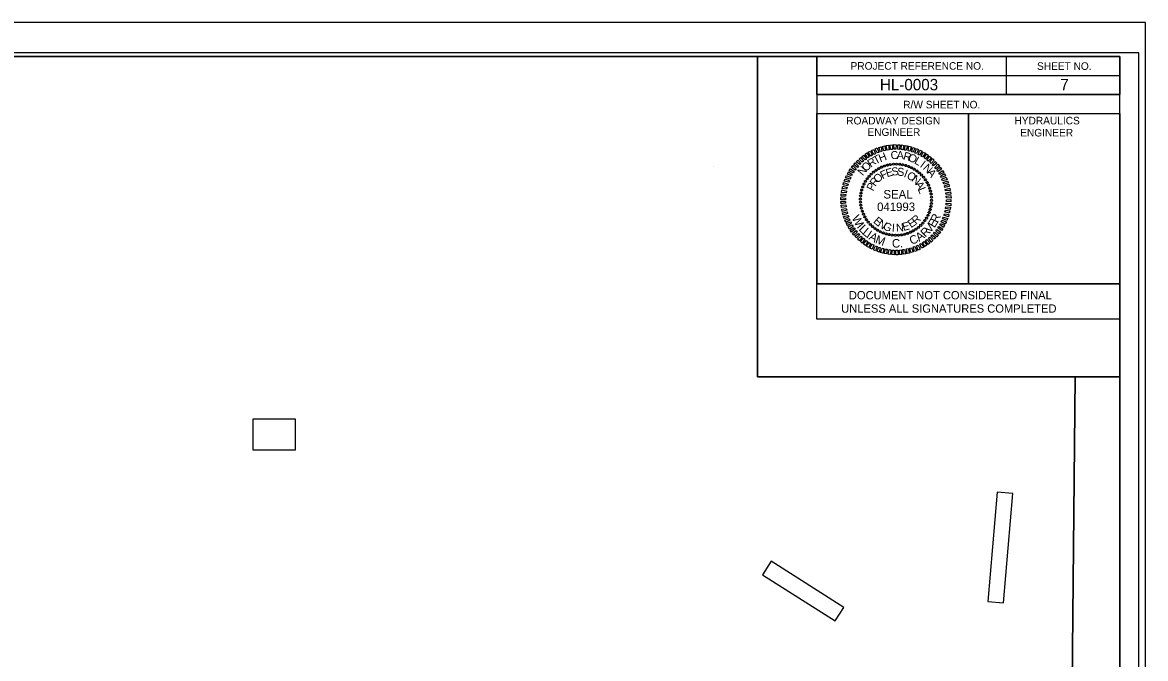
# Model space of a CAD drawing. Extents: x 928111 to 937215, y 684185 to 686530.
# Drawn here: x 932495 to 933237, y 684860 to 685280 of the extents above; entities that cross this region are included whole.
import ezdxf

# ---------------------------------------------------------------- set-up
doc = ezdxf.new("R2010")
doc.units = 0
for name, color, linetype in [('Default', 7, 'Continuous'), ('Matchline', 7, 'Continuous'), ('Prop DSN Text', 7, 'Continuous'), ('Sheet Cutting Line CELL', 7, 'Continuous'), ('Sheet Data Field CELL', 7, 'Continuous'), ('Sheet Layout Plan Border', 7, 'Continuous'), ('Sheet North Arrow Point CELL', 7, 'Continuous'), ('Sheet Plan CELL', 7, 'Continuous'), ('Sheet Plan Layout CELL', 7, 'Continuous'), ('Sheet Plot Border Outside CELL', 7, 'Continuous')]:
    doc.layers.add(name, color=color, linetype=linetype)

msp = doc.modelspace()

# ---------------------------------------------------------------- linework, layer by layer
at = {"layer": 'Default'}
for p, q in [((933060.53, 685183.66), (933060.53, 685183.66)), ((933062.36, 685184.6), (933062.36, 685184.6)), ((933064.24, 685185.35), (933064.24, 685185.35)), ((933066.2, 685185.91), (933066.2, 685185.91)), ((933068.27, 685186.29), (933068.27, 685186.29)), ((933070.28, 685186.57), (933070.28, 685186.57)), ((933072.34, 685186.62), (933072.34, 685186.62)), ((933074.41, 685186.48), (933074.41, 685186.48)), ((933076.42, 685186.15), (933076.42, 685186.15)), ((933078.39, 685185.73), (933078.39, 685185.73)), ((933080.36, 685185.07), (933080.36, 685185.07)), ((933082.24, 685184.23), (933082.24, 685184.23)), ((933052.89, 685176.91), (933052.89, 685176.91)), ((933054.16, 685178.55), (933054.16, 685178.55)), ((933055.56, 685180.01), (933055.56, 685180.01)), ((933057.11, 685181.41), (933057.11, 685181.41)), ((933058.75, 685182.59), (933058.75, 685182.59)), ((933084.06, 685183.29), (933084.06, 685183.29)), ((933085.75, 685182.12), (933085.75, 685182.12)), ((933087.39, 685180.85), (933087.39, 685180.85)), ((933088.84, 685179.45), (933088.84, 685179.45)), ((933090.25, 685177.9), (933090.25, 685177.9)), ((933091.42, 685176.26), (933091.42, 685176.26)), ((933049.28, 685169.55), (933049.28, 685169.55)), ((933049.94, 685171.52), (933049.94, 685171.52)), ((933050.78, 685173.4), (933050.78, 685173.4)), ((933051.72, 685175.23), (933051.72, 685175.23)), ((933092.5, 685174.48), (933092.5, 685174.48)), ((933093.44, 685172.65), (933093.44, 685172.65)), ((933094.19, 685170.77), (933094.19, 685170.77)), ((933048.39, 685163.51), (933048.39, 685163.51)), ((933048.44, 685161.45), (933048.44, 685161.45)), ((933048.53, 685165.57), (933048.53, 685165.57)), ((933048.86, 685167.59), (933048.86, 685167.59)), ((933071.92, 685163.09), (933071.92, 685163.09)), ((933094.75, 685168.8), (933094.75, 685168.8)), ((933095.13, 685166.74), (933095.13, 685166.74)), ((933095.41, 685164.73), (933095.41, 685164.73)), ((933095.45, 685162.66), (933095.45, 685162.66)), ((933048.72, 685159.43), (933048.72, 685159.43)), ((933049.09, 685157.37), (933049.09, 685157.37)), ((933049.66, 685155.4), (933049.66, 685155.4)), ((933093.91, 685154.65), (933093.91, 685154.65)), ((933094.56, 685156.62), (933094.56, 685156.62)), ((933094.99, 685158.59), (933094.99, 685158.59)), ((933095.31, 685160.6), (933095.31, 685160.6)), ((933050.41, 685153.52), (933050.41, 685153.52)), ((933051.34, 685151.7), (933051.34, 685151.7)), ((933052.42, 685149.91), (933052.42, 685149.91)), ((933053.59, 685148.27), (933053.59, 685148.27)), ((933055, 685146.73), (933055, 685146.73)), ((933089.69, 685147.62), (933089.69, 685147.62)), ((933090.95, 685149.26), (933090.95, 685149.26)), ((933092.13, 685150.95), (933092.13, 685150.95)), ((933093.06, 685152.77), (933093.06, 685152.77)), ((933056.45, 685145.32), (933056.45, 685145.32)), ((933058.09, 685144.05), (933058.09, 685144.05)), ((933059.78, 685142.88), (933059.78, 685142.88)), ((933061.61, 685141.95), (933061.61, 685141.95)), ((933063.49, 685141.1), (933063.49, 685141.1)), ((933065.45, 685140.45), (933065.45, 685140.45)), ((933067.42, 685140.02), (933067.42, 685140.02)), ((933069.44, 685139.7), (933069.44, 685139.7)), ((933071.5, 685139.55), (933071.5, 685139.55)), ((933073.56, 685139.6), (933073.56, 685139.6)), ((933075.58, 685139.88), (933075.58, 685139.88)), ((933077.64, 685140.26), (933077.64, 685140.26)), ((933079.61, 685140.82), (933079.61, 685140.82)), ((933081.49, 685141.57), (933081.49, 685141.57)), ((933083.31, 685142.51), (933083.31, 685142.51)), ((933085.09, 685143.59), (933085.09, 685143.59)), ((933086.74, 685144.76), (933086.74, 685144.76)), ((933088.28, 685146.16), (933088.28, 685146.16))]:
    msp.add_line(p, q, dxfattribs=at)
for points in [[(933063.95, 685195.38), (933062.97, 685198.34), (933064.56, 685198.66), (933064.94, 685195.62)], [(933066.2, 685195.9), (933065.45, 685198.9), (933067, 685199.04), (933067.33, 685196.04)], [(933068.45, 685196.18), (933067.94, 685199.18), (933069.53, 685199.37), (933069.58, 685196.32)], [(933070.8, 685196.41), (933070.56, 685199.46), (933072.11, 685199.41), (933071.92, 685196.37)], [(933073.05, 685196.37), (933073.05, 685199.41), (933074.59, 685199.37), (933074.17, 685196.32)], [(933075.39, 685196.23), (933075.58, 685199.27), (933077.13, 685198.99), (933076.52, 685196.04)], [(933077.64, 685195.85), (933078.06, 685198.85), (933079.61, 685198.62), (933078.77, 685195.71)], [(933051.49, 685189.34), (933049.47, 685191.59), (933050.74, 685192.57), (933052.38, 685189.95)], [(933053.27, 685190.74), (933051.53, 685193.13), (933052.75, 685194.02), (933054.3, 685191.3)], [(933055.33, 685191.91), (933053.59, 685194.45), (933055.05, 685195.2), (933056.22, 685192.48)], [(933057.34, 685193.04), (933055.84, 685195.66), (933057.3, 685196.32), (933058.38, 685193.46)], [(933059.41, 685194.02), (933058.19, 685196.74), (933059.59, 685197.3), (933060.58, 685194.3)], [(933061.7, 685194.77), (933060.63, 685197.59), (933062.08, 685198.01), (933062.69, 685195.1)], [(933080.03, 685195.34), (933080.5, 685198.38), (933082.09, 685198.01), (933081.02, 685195.1)], [(933082.28, 685194.73), (933082.99, 685197.63), (933084.44, 685197.16), (933083.27, 685194.4)], [(933084.39, 685193.88), (933085.47, 685196.84), (933086.78, 685196.27), (933085.47, 685193.55)], [(933086.5, 685192.99), (933087.67, 685195.76), (933089.13, 685195.1), (933087.53, 685192.48)], [(933088.66, 685191.91), (933089.92, 685194.59), (933091.33, 685193.79), (933089.55, 685191.35)], [(933090.49, 685190.65), (933092.13, 685193.37), (933093.34, 685192.38), (933091.52, 685190.09)], [(933092.41, 685189.24), (933094.14, 685191.82), (933095.36, 685190.79), (933093.3, 685188.59)], [(933045.02, 685182.68), (933042.49, 685184.27), (933043.38, 685185.63), (933045.63, 685183.57)], [(933046.42, 685184.46), (933043.99, 685186.29), (933045.02, 685187.51), (933047.08, 685185.3)], [(933048.06, 685186.24), (933045.67, 685188.16), (933046.84, 685189.24), (933048.81, 685186.99)], [(933049.61, 685187.88), (933047.55, 685189.95), (933048.67, 685191.07), (933050.5, 685188.54)], [(933094.19, 685187.79), (933096.11, 685190.23), (933097.24, 685189.1), (933095.08, 685187.09)], [(933095.88, 685186.15), (933097.89, 685188.35), (933099.02, 685187.23), (933096.58, 685185.4)], [(933097.52, 685184.46), (933099.67, 685186.57), (933100.66, 685185.3), (933098.17, 685183.52)], [(933098.92, 685182.63), (933101.22, 685184.6), (933102.11, 685183.24), (933099.49, 685181.74)], [(933040.61, 685174.57), (933037.7, 685175.41), (933038.31, 685176.87), (933041.13, 685175.55)], [(933041.55, 685176.63), (933038.64, 685177.71), (933039.34, 685179.16), (933042.02, 685177.66)], [(933042.49, 685178.79), (933039.81, 685179.96), (933040.52, 685181.41), (933043.05, 685179.68)], [(933043.61, 685180.8), (933040.99, 685182.21), (933041.92, 685183.52), (933044.36, 685181.65)], [(933100.14, 685180.71), (933102.63, 685182.49), (933103.52, 685181.09), (933100.8, 685179.77)], [(933101.36, 685178.65), (933103.99, 685180.29), (933104.59, 685178.84), (933101.92, 685177.76)], [(933102.3, 685176.63), (933105.06, 685178.04), (933105.67, 685176.54), (933102.77, 685175.6)], [(933038.92, 685167.68), (933035.92, 685167.96), (933036.11, 685169.55), (933039.16, 685168.8)], [(933039.3, 685170.07), (933036.39, 685170.45), (933036.72, 685172.04), (933039.67, 685171.05)], [(933039.91, 685172.32), (933037, 685172.93), (933037.33, 685174.48), (933040.28, 685173.3)], [(933103.14, 685174.43), (933106, 685175.65), (933106.52, 685174.2), (933103.61, 685173.45)], [(933103.89, 685172.18), (933106.89, 685173.26), (933107.17, 685171.71), (933104.22, 685171.2)], [(933104.45, 685169.93), (933107.41, 685170.82), (933107.69, 685169.23), (933104.74, 685168.95)], [(933038.69, 685160.74), (933035.64, 685160.37), (933035.55, 685161.96), (933038.59, 685161.87)], [(933038.64, 685163.09), (933035.59, 685162.95), (933035.59, 685164.54), (933038.64, 685164.21)], [(933038.69, 685165.43), (933035.64, 685165.52), (933035.74, 685167.07), (933038.78, 685166.55)], [(933104.88, 685167.68), (933107.92, 685168.34), (933108.06, 685166.74), (933105.06, 685166.55)], [(933105.16, 685165.43), (933108.2, 685165.8), (933108.3, 685164.21), (933105.25, 685164.3)], [(933105.2, 685163.09), (933108.25, 685163.23), (933108.25, 685161.63), (933105.2, 685161.96)], [(933038.97, 685158.49), (933035.92, 685157.84), (933035.78, 685159.43), (933038.78, 685159.62)], [(933039.39, 685156.24), (933036.44, 685155.35), (933036.16, 685156.95), (933039.11, 685157.23)], [(933039.95, 685153.99), (933036.95, 685152.91), (933036.67, 685154.46), (933039.63, 685154.98)], [(933104.55, 685156.1), (933107.45, 685155.73), (933107.13, 685154.13), (933104.17, 685155.12)], [(933104.92, 685158.49), (933107.92, 685158.21), (933107.74, 685156.62), (933104.69, 685157.37)], [(933105.16, 685160.74), (933108.2, 685160.65), (933108.11, 685159.1), (933105.06, 685159.62)], [(933040.7, 685151.74), (933037.84, 685150.52), (933037.33, 685151.98), (933040.24, 685152.73)], [(933041.55, 685149.54), (933038.78, 685148.13), (933038.17, 685149.63), (933041.08, 685150.57)], [(933042.49, 685147.52), (933039.86, 685145.88), (933039.25, 685147.34), (933041.92, 685148.41)], [(933101.36, 685147.38), (933104.03, 685146.21), (933103.33, 685144.76), (933100.8, 685146.49)], [(933102.3, 685149.54), (933105.2, 685148.46), (933104.5, 685147.01), (933101.83, 685148.51)], [(933103.24, 685151.6), (933106.14, 685150.76), (933105.53, 685149.3), (933102.72, 685150.62)], [(933103.94, 685153.85), (933106.84, 685153.24), (933106.52, 685151.7), (933103.56, 685152.87)], [(933043.7, 685145.46), (933041.22, 685143.68), (933040.33, 685145.09), (933043.05, 685146.4)], [(933044.92, 685143.54), (933042.63, 685141.57), (933041.74, 685142.93), (933044.36, 685144.43)], [(933046.33, 685141.71), (933044.17, 685139.6), (933043.19, 685140.87), (933045.67, 685142.65)], [(933047.97, 685140.02), (933045.95, 685137.82), (933044.83, 685138.95), (933047.27, 685140.77)], [(933095.78, 685139.93), (933098.17, 685138.01), (933097, 685136.93), (933095.03, 685139.18)], [(933097.42, 685141.71), (933099.86, 685139.88), (933098.83, 685138.66), (933096.77, 685140.87)], [(933098.83, 685143.49), (933101.36, 685141.9), (933100.47, 685140.54), (933098.22, 685142.6)], [(933100.24, 685145.37), (933102.86, 685143.96), (933101.92, 685142.65), (933099.49, 685144.52)], [(933049.66, 685138.38), (933047.74, 685135.95), (933046.61, 685137.07), (933048.77, 685139.09)], [(933051.44, 685136.93), (933049.7, 685134.35), (933048.49, 685135.38), (933050.55, 685137.59)], [(933053.36, 685135.52), (933051.72, 685132.8), (933050.5, 685133.79), (933052.33, 685136.09)], [(933055.19, 685134.26), (933053.92, 685131.59), (933052.52, 685132.38), (933054.3, 685134.82)], [(933057.34, 685133.18), (933056.17, 685130.41), (933054.72, 685131.07), (933056.31, 685133.7)], [(933059.45, 685132.29), (933058.38, 685129.34), (933057.06, 685129.9), (933058.38, 685132.62)], [(933061.56, 685131.45), (933060.86, 685128.54), (933059.41, 685129.01), (933060.58, 685131.77)], [(933084.44, 685132.15), (933085.66, 685129.43), (933084.25, 685128.87), (933083.27, 685131.87)], [(933086.5, 685133.13), (933088, 685130.51), (933086.55, 685129.85), (933085.47, 685132.71)], [(933088.52, 685134.26), (933090.25, 685131.73), (933088.8, 685130.98), (933087.63, 685133.7)], [(933090.58, 685135.43), (933092.31, 685133.04), (933091.09, 685132.15), (933089.55, 685134.87)], [(933092.36, 685136.84), (933094.38, 685134.59), (933093.11, 685133.6), (933091.47, 685136.23)], [(933094.24, 685138.29), (933096.3, 685136.23), (933095.17, 685135.1), (933093.34, 685137.63)], [(933063.81, 685130.84), (933063.34, 685127.79), (933061.75, 685128.16), (933062.83, 685131.07)], [(933066.2, 685130.32), (933065.78, 685127.32), (933064.24, 685127.55), (933065.08, 685130.46)], [(933068.45, 685129.95), (933068.27, 685126.9), (933066.72, 685127.18), (933067.33, 685130.13)], [(933070.8, 685129.8), (933070.8, 685126.76), (933069.25, 685126.8), (933069.67, 685129.85)], [(933073.05, 685129.76), (933073.28, 685126.71), (933071.74, 685126.76), (933071.92, 685129.8)], [(933075.39, 685129.99), (933075.91, 685126.99), (933074.31, 685126.8), (933074.27, 685129.85)], [(933077.64, 685130.27), (933078.39, 685127.27), (933076.84, 685127.13), (933076.52, 685130.13)], [(933079.89, 685130.79), (933080.88, 685127.84), (933079.28, 685127.51), (933078.91, 685130.55)], [(933082.14, 685131.4), (933083.22, 685128.59), (933081.77, 685128.16), (933081.16, 685131.07)]]:
    msp.add_lwpolyline(points, close=True, dxfattribs=at)
for centre, major_axis in [((933060.52, 685183.65), (-0.327, 0.59)), ((933062.36, 685184.57), (-0.275, 0.617)), ((933064.27, 685185.32), (-0.22, 0.638)), ((933066.23, 685185.9), (-0.163, 0.655)), ((933068.24, 685186.31), (-0.106, 0.667)), ((933070.28, 685186.54), (-0.047, 0.673)), ((933072.33, 685186.59), (0.012, 0.675)), ((933074.38, 685186.47), (0.071, 0.671)), ((933076.41, 685186.17), (0.129, 0.663)), ((933078.4, 685185.69), (0.186, 0.649)), ((933080.35, 685185.04), (0.242, 0.63)), ((933082.23, 685184.22), (0.296, 0.607)), ((933084.03, 685183.24), (0.348, 0.579)), ((933052.9, 685176.91), (-0.546, 0.397)), ((933054.18, 685178.51), (-0.509, 0.443)), ((933055.59, 685180), (-0.469, 0.486)), ((933057.13, 685181.36), (-0.425, 0.525)), ((933058.77, 685182.58), (-0.377, 0.56)), ((933085.74, 685182.11), (0.397, 0.546)), ((933087.35, 685180.83), (0.443, 0.509)), ((933088.84, 685179.42), (0.486, 0.469)), ((933090.2, 685177.88), (0.525, 0.425)), ((933091.42, 685176.23), (0.56, 0.377)), ((933049.32, 685169.57), (-0.649, 0.186)), ((933049.97, 685171.51), (-0.63, 0.242)), ((933050.79, 685173.39), (-0.607, 0.296)), ((933051.77, 685175.2), (-0.579, 0.348)), ((933092.49, 685174.49), (0.59, 0.327)), ((933093.4, 685172.65), (0.617, 0.275)), ((933094.15, 685170.74), (0.638, 0.22)), ((933094.74, 685168.77), (0.655, 0.163)), ((933048.41, 685163.5), (-0.675, 0.012)), ((933048.47, 685161.45), (-0.673, -0.047)), ((933048.54, 685165.54), (-0.671, 0.071)), ((933048.84, 685167.57), (-0.663, 0.129)), ((933095.15, 685166.76), (0.667, 0.106)), ((933095.38, 685164.73), (0.673, 0.047)), ((933095.43, 685162.68), (0.675, -0.012)), ((933048.7, 685159.41), (-0.667, -0.106)), ((933049.11, 685157.4), (-0.655, -0.163)), ((933049.69, 685155.43), (-0.638, -0.22)), ((933050.44, 685153.52), (-0.617, -0.275)), ((933093.87, 685154.66), (0.63, -0.242)), ((933094.52, 685156.61), (0.649, -0.186)), ((933095, 685158.6), (0.663, -0.129)), ((933095.31, 685160.63), (0.671, -0.071)), ((933051.36, 685151.69), (-0.59, -0.327)), ((933052.43, 685149.94), (-0.56, -0.377)), ((933053.65, 685148.29), (-0.525, -0.425)), ((933055.01, 685146.75), (-0.486, -0.469)), ((933088.26, 685146.17), (0.469, -0.486)), ((933089.67, 685147.66), (0.509, -0.443)), ((933090.94, 685149.27), (0.546, -0.397)), ((933092.08, 685150.98), (0.579, -0.348)), ((933093.06, 685152.78), (0.607, -0.296)), ((933056.5, 685145.34), (-0.443, -0.509)), ((933058.1, 685144.06), (-0.397, -0.546)), ((933059.81, 685142.93), (-0.348, -0.579)), ((933061.62, 685141.95), (-0.296, -0.607)), ((933063.5, 685141.14), (-0.242, -0.63)), ((933065.44, 685140.48), (-0.186, -0.649)), ((933067.44, 685140.01), (-0.129, -0.663)), ((933069.47, 685139.7), (-0.071, -0.671)), ((933071.51, 685139.58), (-0.012, -0.675)), ((933073.56, 685139.63), (0.047, -0.673)), ((933075.6, 685139.86), (0.106, -0.667)), ((933077.61, 685140.27), (0.163, -0.655)), ((933079.58, 685140.85), (0.22, -0.638)), ((933081.49, 685141.61), (0.275, -0.617)), ((933083.32, 685142.52), (0.327, -0.59)), ((933085.07, 685143.59), (0.377, -0.56)), ((933086.72, 685144.81), (0.425, -0.525))]:
    msp.add_ellipse(centre, major_axis=major_axis, ratio=0.999708, dxfattribs=at)
at = {"layer": 'Matchline'}
msp.add_line((933190.31, 685046.18), (933181.74, 684207.66), dxfattribs=at)
at = {"layer": 'Prop DSN Text'}
for points in [[(932647.35, 685018.39), (932675.14, 685018.39), (932675.14, 684997.73), (932647.35, 684997.73)], [(933142.94, 684896.89), (933149.08, 684969.12), (933138.69, 684970), (933132.56, 684897.77)], [(932983.83, 684915.4), (933031.66, 684884.85), (933037.42, 684893.86), (932989.58, 684924.42)]]:
    msp.add_lwpolyline(points, close=True, dxfattribs=at)
at = {"layer": 'Sheet Cutting Line CELL'}
msp.add_line((933236.79, 685280.15), (931553.29, 685280.15), dxfattribs=at)
at = {"layer": 'Sheet Layout Plan Border'}
msp.add_line((933181.74, 684207.66), (933190.31, 685046.18), dxfattribs=at)
at = {"layer": 'Sheet North Arrow Point CELL'}
msp.add_line((932951.67, 685184.73), (932951.67, 685184.73), dxfattribs=at)
at = {"layer": 'Sheet Plan CELL'}
for p, q in [((933144.75, 685257.6), (933144.8, 685232.6)), ((933019.73, 685245.13), (933219.78, 685245.11)), ((933019.74, 685232.59), (933219.78, 685232.61)), ((933019.74, 685232.59), (933019.74, 685220.1)), ((933119.79, 685220.1), (933119.8, 685107.64)), ((933019.75, 685084.11), (933019.75, 685107.61)), ((933019.75, 685107.61), (933219.79, 685107.61)), ((933219.79, 685107.6), (933219.79, 685084.1)), ((933219.79, 685084.11), (933019.75, 685084.11))]:
    msp.add_line(p, q, dxfattribs=at)
for points in [[(931566.29, 684205.15), (933232.28, 684205.16), (933232.29, 685260.15), (931566.29, 685260.15)], [(931719.78, 684207.66), (931719.75, 685257.64), (933019.74, 685257.68), (933019.75, 685107.61), (933219.79, 685107.6), (933219.79, 684207.66)], [(933219.81, 685257.66), (931719.78, 685257.66), (931719.78, 684207.66), (933219.79, 684207.66)], [(932980.53, 685046.18), (933219.8, 685046.18), (933219.83, 685257.66), (932980.53, 685257.66)], [(933019.74, 685257.68), (933219.81, 685257.66), (933219.78, 685232.61), (933019.74, 685232.59)], [(933019.74, 685220.1), (933119.79, 685220.1), (933119.79, 685107.59), (933019.75, 685107.61)], [(933119.79, 685220.1), (933219.78, 685220.11), (933219.79, 685107.6), (933119.79, 685107.59)]]:
    msp.add_lwpolyline(points, close=True, dxfattribs=at)
at = {"layer": 'Sheet Plan Layout CELL'}
msp.add_lwpolyline([(931719.75, 685257.64), (931719.78, 684207.66), (933219.78, 684207.66), (933219.78, 685046.18), (932980.53, 685046.18), (932980.53, 685257.66)], close=True, dxfattribs=at)
at = {"layer": 'Sheet Plot Border Outside CELL'}
msp.add_lwpolyline([(931553.29, 684185.15), (933236.79, 684185.15), (933236.79, 685280.15), (931553.29, 685280.15)], close=True, dxfattribs=at)

# ---------------------------------------------------------------- texts
at = {"layer": 'Default'}
for s, height, rotation, p in [('T', 5.29, 27.81977, (933058.52, 685186.24)), ('H', 5.29, 20.61948, (933061.56, 685187.79)), ('C', 5.29, 6.21987, (933068.69, 685189.66)), ('A', 5.29, 359.02032, (933072.39, 685189.95)), ('R', 5.29, 344.6211, (933076.33, 685189.76)), ('O', 5.29, 337.42116, (933079.47, 685189.05)), ('L', 5.29, 330.22087, (933083.59, 685187.32)), ('N', 5.29, 49.4235, (933049.94, 685178.55)), ('O', 5.29, 42.22174, (933052.09, 685181.27)), ('R', 5.29, 35.02051, (933055.33, 685184.18)), ('E', 5.29, 16.61107, (933066.06, 685177.9)), ('S', 5.29, 7.25561, (933069.3, 685178.88)), ('S', 5.29, 357.9004, (933072.67, 685178.93)), ('I', 5.29, 323.02014, (933087.39, 685185.07)), ('N', 5.29, 315.81891, (933089.41, 685183.62)), ('R', 5.29, 54.03965, (933058.33, 685171.43)), ('O', 5.29, 44.68124, (933059.97, 685173.73)), ('F', 5.29, 25.96703, (933063.06, 685176.49)), ('I', 5.29, 339.1896, (933076.7, 685178.27)), ('O', 5.29, 329.83348, (933078.58, 685177.62)), ('N', 5.29, 320.47661, (933081.72, 685175.74)), ('A', 5.29, 308.61715, (933092.17, 685180.85)), ('P', 5.29, 63.39889, (933056.83, 685168.43)), ('SEAL', 5.623, 360, (933063.67, 685163.88)), ('A', 5.29, 301.76027, (933084.39, 685173.3)), ('L', 5.29, 292.40085, (933086.22, 685170.07)), ('041993', 5.623, 360, (933059.45, 685155.58)), ('W', 5.62, 298.3574, (933042.48, 685151.12)), ('I', 5.62, 310.89147, (933045.78, 685145.02)), ('L', 5.62, 314.69342, (933047.03, 685143.32)), ('E', 5.29, 318.27689, (933056.55, 685148.41)), ('N', 5.29, 327.63396, (933059.36, 685145.88)), ('G', 5.29, 336.99024, (933062.92, 685143.77)), ('I', 5.29, 355.7012, (933069.06, 685141.99)), ('N', 5.29, 5.05639, (933072.2, 685141.85)), ('E', 5.29, 14.41176, (933076.84, 685142.41)), ('E', 5.29, 33.12409, (933081.81, 685144.24)), ('R', 5.29, 42.48141, (933085.14, 685146.45)), ('V', 5.62, 51.33406, (933094.43, 685140.65)), ('E', 5.62, 59.58708, (933097.42, 685144.11)), ('R', 5.62, 66.69642, (933099.57, 685147.41)), ('L', 5.62, 320.96819, (933049.34, 685140.72)), ('I', 5.62, 327.24295, (933051.92, 685138.39)), ('A', 5.62, 331.0449, (933053.6, 685137.11)), ('M', 5.62, 339.88521, (933057.81, 685134.61)), ('C', 5.62, 25.43134, (933082.37, 685133.07)), ('A', 5.62, 35.01349, (933087.22, 685135.23)), ('R', 5.62, 43.8538, (933091.32, 685137.91)), ('C', 5.62, 1.61506, (933069.36, 685131.41)), ('.', 5.62, 11.19721, (933074.67, 685131.42))]:
    msp.add_text(s, height=height, rotation=rotation, dxfattribs=at).set_placement(p)
at = {"layer": 'Sheet Data Field CELL'}
for s, p in [('HL-0003', (933061.31, 685235.35)), ('7', (933180.51, 685235.41))]:
    msp.add_text(s, height=7.5, rotation=0, dxfattribs=at).set_placement(p)
at = {"layer": 'Sheet Plan CELL'}
for s, height, p in [('PROJECT REFERENCE NO.', 5.0001, (933041.94, 685248.95)), ('SHEET NO.', 5, (933165.1, 685248.84)), ('R/W SHEET NO.', 5.0001, (933076.74, 685223.4)), ('ROADWAY DESIGN', 5.0001, (933039.11, 685212.8)), ('HYDRAULICS', 5, (933150.25, 685212.83)), ('ENGINEER', 5, (933053.1, 685205.26)), ('ENGINEER', 5, (933154.01, 685204.86))]:
    msp.add_text(s, height=height, rotation=0, dxfattribs=at).set_placement(p)
for s, p in [('DOCUMENT NOT CONSIDERED FINAL', (933040.82, 685097.27)), ('UNLESS ALL SIGNATURES COMPLETED', (933035.75, 685088.47))]:
    msp.add_text(s, height=5.5, dxfattribs=at).set_placement(p)

doc.saveas('drawing.dxf')
